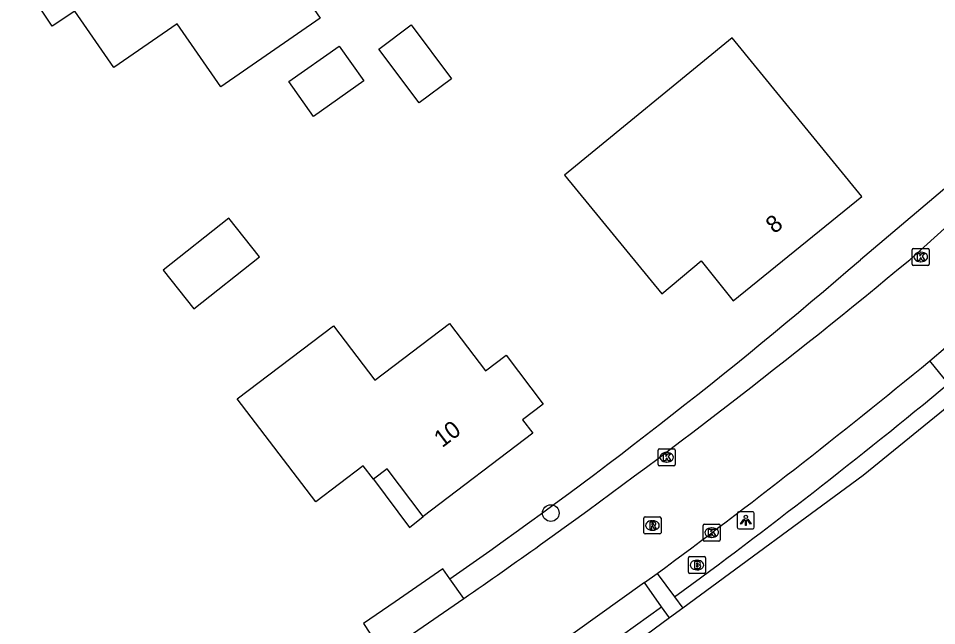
# Model space of a CAD drawing. Extents: x 162675 to 163482, y 379761 to 381227.
# Drawn here: x 163198.8 to 163252.7, y 380978.5 to 381014.2 of the extents above; entities that cross this region are included whole.
import ezdxf

# ---------------------------------------------------------------- set-up
doc = ezdxf.new("R2010")
doc.units = 0
for name, color, linetype in [('IMGEO_Boom', 7, 'Continuous'), ('IMGEO_Brandkraan', 7, 'Continuous'), ('IMGEO_Groenvoorziening', 7, 'Continuous'), ('IMGEO_Kolk', 7, 'Continuous'), ('IMGEO_Lichtpunt', 7, 'Continuous'), ('IMGEO_Pand', 7, 'Continuous'), ('IMGEO_Pand_nummerreeks', 7, 'Continuous'), ('IMGEO_Pand_overbouw', 7, 'Continuous'), ('IMGEO_Parkeervlak_halfverhard', 7, 'Continuous'), ('IMGEO_Rijbaan_lokaal_gesloten', 7, 'Continuous'), ('IMGEO_Rijbaan_lokaal_open', 7, 'Continuous'), ('IMGEO_Rioolput', 7, 'Continuous'), ('IMGEO_Voetpad_open', 7, 'Continuous')]:
    doc.layers.add(name, color=color, linetype=linetype)

msp = doc.modelspace()

# ---------------------------------------------------------------- linework, layer by layer
at = {"layer": 'IMGEO_Boom'}
msp.add_circle((163230.072, 380985.135), 0.489, dxfattribs=at)
at = {"layer": 'IMGEO_Brandkraan'}
for p, q in [((163238.222, 380982.585), (163239.074, 380982.585)), ((163238.147, 380981.659), (163238.147, 380982.511)), ((163238.635, 380982.365), (163238.66, 380982.365)), ((163239.148, 380982.511), (163239.148, 380981.659)), ((163239.074, 380981.585), (163238.222, 380981.585)), ((163238.658, 380981.805), (163238.633, 380981.805))]:
    msp.add_line(p, q, dxfattribs=at)
for points in [[(163238.222, 380982.585), (163239.074, 380982.585)], [(163238.147, 380981.659), (163238.147, 380982.511)], [(163238.495, 380982.285), (163238.495, 380981.885), (163238.708, 380981.885)], [(163238.726, 380982.285), (163238.495, 380982.285)], [(163238.674, 380982.204), (163238.62, 380982.204), (163238.62, 380982.128)], [(163238.62, 380982.128), (163238.673, 380982.128)], [(163238.682, 380982.052), (163238.62, 380982.052), (163238.62, 380981.971)], [(163239.148, 380982.511), (163239.148, 380981.659)], [(163239.074, 380981.585), (163238.222, 380981.585)], [(163238.62, 380981.971), (163238.682, 380981.971)]]:
    msp.add_lwpolyline(points, dxfattribs=at)
for centre, radius, start, end in [((163238.224, 380982.509), 0.0765, 91.552, 178.448), ((163238.224, 380982.509), 0.0765, 91.552, 178.448), ((163239.072, 380982.509), 0.0765, 1.552, 88.448), ((163239.072, 380982.509), 0.0765, 1.552, 88.448), ((163238.675, 380982.166), 0.0379, 267.8285, 90.9355), ((163238.683, 380982.011), 0.0404, 269.8759, 90.5077), ((163238.73, 380982.14), 0.145, 59.4692, 91.5367), ((163238.755, 380982.187), 0.0922, 285.5137, 58.1501), ((163238.76, 380981.995), 0.105, 301.3115, 78.989), ((163238.224, 380981.661), 0.0765, 181.552, 268.448), ((163238.224, 380981.661), 0.0765, 181.552, 268.448), ((163238.714, 380982.136), 0.251, 268.6676, 293.5347), ((163239.072, 380981.661), 0.0765, 271.552, 358.448), ((163239.072, 380981.661), 0.0765, 271.552, 358.448)]:
    msp.add_arc(centre, radius, start, end, dxfattribs=at)
for centre, major_axis, ratio, start_param, end_param in [((163238.634, 380982.085), (-0.387, 0.002), 0.722429, 4.712389, 7.853982), ((163238.659, 380982.085), (-0.39, 0.002), 0.717154, 1.570796, 4.712389)]:
    msp.add_ellipse(centre, major_axis=major_axis, ratio=ratio, start_param=start_param, end_param=end_param, dxfattribs=at)
at = {"layer": 'IMGEO_Groenvoorziening'}
for points in [[(163282.912, 381031.92), (163281.455, 381030.578), (163266.746, 381016.75), (163259.983, 381010.203), (163254.178, 381005.02), (163248.231, 381000)], [(163254.038, 380991.932), (163248.395, 380987.338), (163237.811, 380979.548)], [(163237.042, 380978.982), (163231.716, 380975.062)]]:
    msp.add_lwpolyline(points, dxfattribs=at)
msp.add_arc((163058.673, 381218.917), 289.58, 304.85117, 310.88892, dxfattribs=at)
at = {"layer": 'IMGEO_Kolk'}
for p, q in [((163251.27, 380999.734), (163251.27, 381000.586)), ((163251.345, 381000.66), (163252.197, 381000.66)), ((163251.758, 381000.44), (163251.783, 381000.44)), ((163252.271, 381000.586), (163252.271, 380999.734)), ((163251.781, 380999.88), (163251.756, 380999.88)), ((163252.197, 380999.66), (163251.345, 380999.66)), ((163236.368, 380987.982), (163236.368, 380988.834)), ((163236.443, 380988.908), (163237.295, 380988.908)), ((163236.856, 380988.688), (163236.881, 380988.688)), ((163237.369, 380988.834), (163237.369, 380987.982)), ((163236.879, 380988.128), (163236.854, 380988.128)), ((163237.295, 380987.908), (163236.443, 380987.908)), ((163239.01, 380983.558), (163239.01, 380984.41)), ((163239.085, 380984.484), (163239.937, 380984.484)), ((163239.498, 380984.264), (163239.523, 380984.264)), ((163240.011, 380984.41), (163240.011, 380983.558)), ((163239.521, 380983.704), (163239.496, 380983.704)), ((163239.937, 380983.484), (163239.085, 380983.484))]:
    msp.add_line(p, q, dxfattribs=at)
for points in [[(163251.27, 380999.734), (163251.27, 381000.586)], [(163251.345, 381000.66), (163252.197, 381000.66)], [(163251.591, 381000.36), (163251.714, 381000.36), (163251.714, 381000.209), (163251.844, 381000.36), (163252.008, 381000.36), (163251.862, 381000.209), (163252.015, 380999.96), (163251.863, 380999.96), (163251.778, 381000.124), (163251.714, 381000.057), (163251.714, 380999.96), (163251.591, 380999.96), (163251.591, 381000.36)], [(163252.271, 381000.586), (163252.271, 380999.734)], [(163252.197, 380999.66), (163251.345, 380999.66)], [(163236.368, 380987.982), (163236.368, 380988.834)], [(163236.443, 380988.908), (163237.295, 380988.908)], [(163236.689, 380988.608), (163236.812, 380988.608), (163236.812, 380988.457), (163236.942, 380988.608), (163237.106, 380988.608), (163236.96, 380988.457), (163237.113, 380988.208), (163236.961, 380988.208), (163236.876, 380988.372), (163236.812, 380988.305), (163236.812, 380988.208), (163236.689, 380988.208), (163236.689, 380988.608)], [(163237.369, 380988.834), (163237.369, 380987.982)], [(163237.295, 380987.908), (163236.443, 380987.908)], [(163239.01, 380983.558), (163239.01, 380984.41)], [(163239.085, 380984.484), (163239.937, 380984.484)], [(163240.011, 380984.41), (163240.011, 380983.558)], [(163239.331, 380984.184), (163239.454, 380984.184), (163239.454, 380984.033), (163239.584, 380984.184), (163239.748, 380984.184), (163239.602, 380984.033), (163239.755, 380983.784), (163239.603, 380983.784), (163239.518, 380983.948), (163239.454, 380983.881), (163239.454, 380983.784), (163239.331, 380983.784), (163239.331, 380984.184)], [(163239.937, 380983.484), (163239.085, 380983.484)]]:
    msp.add_lwpolyline(points, dxfattribs=at)
for centre, start, end in [((163251.347, 381000.584), 91.552, 178.448), ((163251.347, 381000.584), 91.552, 178.448), ((163252.195, 381000.584), 1.552, 88.448), ((163252.195, 381000.584), 1.552, 88.448), ((163251.347, 380999.736), 181.552, 268.448), ((163251.347, 380999.736), 181.552, 268.448), ((163252.195, 380999.736), 271.552, 358.448), ((163252.195, 380999.736), 271.552, 358.448), ((163236.445, 380988.832), 91.552, 178.448), ((163236.445, 380988.832), 91.552, 178.448), ((163237.293, 380988.832), 1.552, 88.448), ((163237.293, 380988.832), 1.552, 88.448), ((163236.445, 380987.984), 181.552, 268.448), ((163236.445, 380987.984), 181.552, 268.448), ((163237.293, 380987.984), 271.552, 358.448), ((163237.293, 380987.984), 271.552, 358.448), ((163239.087, 380984.408), 91.552, 178.448), ((163239.087, 380984.408), 91.552, 178.448), ((163239.935, 380984.408), 1.552, 88.448), ((163239.935, 380984.408), 1.552, 88.448), ((163239.087, 380983.56), 181.552, 268.448), ((163239.087, 380983.56), 181.552, 268.448), ((163239.935, 380983.56), 271.552, 358.448), ((163239.935, 380983.56), 271.552, 358.448)]:
    msp.add_arc(centre, 0.0765, start, end, dxfattribs=at)
for centre, major_axis, ratio, start_param, end_param in [((163251.757, 381000.16), (-0.387, 0.002), 0.722429, 4.712389, 7.853982), ((163251.782, 381000.16), (-0.39, 0.002), 0.717154, 1.570796, 4.712389), ((163236.855, 380988.408), (-0.387, 0.002), 0.722429, 4.712389, 7.853982), ((163236.88, 380988.408), (-0.39, 0.002), 0.717154, 1.570796, 4.712389), ((163239.497, 380983.984), (-0.387, 0.002), 0.722429, 4.712389, 7.853982), ((163239.522, 380983.984), (-0.39, 0.002), 0.717154, 1.570796, 4.712389)]:
    msp.add_ellipse(centre, major_axis=major_axis, ratio=ratio, start_param=start_param, end_param=end_param, dxfattribs=at)
at = {"layer": 'IMGEO_Lichtpunt'}
for p, q in [((163241.013, 380985.112), (163241.013, 380984.305)), ((163241.013, 380985.112), (163241.013, 380984.305)), ((163241.915, 380985.207), (163241.107, 380985.207)), ((163241.915, 380985.207), (163241.107, 380985.207)), ((163242.009, 380984.305), (163242.009, 380985.112)), ((163242.009, 380984.305), (163242.009, 380985.112)), ((163241.107, 380984.211), (163241.915, 380984.211)), ((163241.107, 380984.211), (163241.915, 380984.211))]:
    msp.add_line(p, q, dxfattribs=at)
for points in [[(163241.387, 380984.776), (163241.426, 380984.748), (163241.238, 380984.486), (163241.2, 380984.513), (163241.387, 380984.776)], [(163241.599, 380984.748), (163241.637, 380984.775), (163241.824, 380984.513), (163241.785, 380984.485), (163241.599, 380984.748)], [(163241.489, 380984.728), (163241.536, 380984.728), (163241.536, 380984.406), (163241.489, 380984.406), (163241.489, 380984.728)]]:
    msp.add_lwpolyline(points, dxfattribs=at)
msp.add_circle((163241.512, 380984.91), 0.0994, dxfattribs=at)
for centre, start, end in [((163241.107, 380985.112), 90, 180), ((163241.107, 380985.112), 90, 180), ((163241.915, 380985.112), 0, 90), ((163241.915, 380985.112), 0, 90), ((163241.107, 380984.305), 180, 270), ((163241.107, 380984.305), 180, 270), ((163241.915, 380984.305), 270, 0), ((163241.915, 380984.305), 270, 360)]:
    msp.add_arc(centre, 0.0946, start, end, dxfattribs=at)
at = {"layer": 'IMGEO_Pand'}
for points in [[(163216.549, 381014.172), (163210.72, 381010.136), (163208.153, 381013.844), (163204.436, 381011.271), (163202.152, 381014.57), (163200.83, 381013.694), (163198.84, 381016.694), (163200.116, 381017.54), (163199.546, 381018.361), (163203.321, 381020.977), (163203.891, 381020.155), (163206.772, 381022.138), (163209.333, 381018.435), (163212.214, 381020.433), (163216.549, 381014.172)], [(163219.991, 381012.346), (163221.872, 381013.775), (163224.243, 381010.614), (163222.354, 381009.197), (163219.991, 381012.346)], [(163236.593, 380998.002), (163238.893, 380999.927), (163240.777, 380997.592), (163248.313, 381003.716), (163240.711, 381013.015), (163230.875, 381004.965), (163236.593, 380998.002)], [(163216.143, 381008.407), (163214.704, 381010.446), (163217.663, 381012.533), (163219.101, 381010.493), (163216.143, 381008.407)], [(163207.332, 380999.388), (163209.133, 380997.114), (163212.983, 381000.163), (163211.182, 381002.437), (163207.332, 380999.388)], [(163224.127, 380996.263), (163226.243, 380993.477), (163227.446, 380994.39), (163229.622, 380991.525), (163228.421, 380990.613), (163229.026, 380989.817), (163222.587, 380984.931), (163220.472, 380987.722), (163219.676, 380987.115), (163219.073, 380987.913), (163216.292, 380985.792), (163211.684, 380991.836), (163217.329, 380996.122), (163219.748, 380992.938), (163224.127, 380996.263)]]:
    msp.add_lwpolyline(points, dxfattribs=at)
at = {"layer": 'IMGEO_Pand_overbouw'}
msp.add_lwpolyline([(163219.676, 380987.115), (163221.791, 380984.29), (163222.587, 380984.931), (163220.472, 380987.722)], close=True, dxfattribs=at)
at = {"layer": 'IMGEO_Parkeervlak_halfverhard'}
msp.add_lwpolyline([(163231.219, 380975.805), (163236.566, 380979.628)], dxfattribs=at)
msp.add_arc((163038.879, 381251.775), 336.342, 306.1573, 309.62868, dxfattribs=at)
at = {"layer": 'IMGEO_Rijbaan_lokaal_gesloten'}
for points in [[(163283.96, 381030.703), (163274.447, 381021.832), (163256.625, 381004.958), (163251.131, 380999.999)], [(163252.298, 380994.062), (163253.218, 380994.843)], [(163235.565, 380981.053), (163236.302, 380981.59)], [(163235.565, 380981.053), (163230.185, 380977.209)], [(163220.253, 380976.891), (163221.325, 380977.616), (163221.696, 380977.871), (163224.966, 380980.12)]]:
    msp.add_lwpolyline(points, dxfattribs=at)
for centre, radius, start, end in [((163002.35, 381300.051), 389.773, 305.63961, 309.66302), ((163009.458, 381289.023), 382.065, 306.42229, 309.46444), ((162993.378, 381314.308), 406.589, 304.72145, 305.49645)]:
    msp.add_arc(centre, radius, start, end, dxfattribs=at)
at = {"layer": 'IMGEO_Rijbaan_lokaal_open'}
for points in [[(163224.153, 380981.276), (163223.746, 380981.856), (163220.946, 380979.931), (163219.083, 380978.649), (163219.461, 380978.08)], [(163224.966, 380980.12), (163224.153, 380981.276)]]:
    msp.add_lwpolyline(points, dxfattribs=at)
at = {"layer": 'IMGEO_Rioolput'}
for p, q in [((163235.535, 380983.982), (163235.535, 380984.834)), ((163235.61, 380984.908), (163236.462, 380984.908)), ((163236.536, 380984.834), (163236.536, 380983.982)), ((163236.023, 380984.688), (163236.048, 380984.688)), ((163236.462, 380983.908), (163235.61, 380983.908)), ((163236.046, 380984.128), (163236.021, 380984.128))]:
    msp.add_line(p, q, dxfattribs=at)
for points in [[(163235.535, 380983.982), (163235.535, 380984.834)], [(163235.61, 380984.908), (163236.462, 380984.908)], [(163236.536, 380984.834), (163236.536, 380983.982)], [(163236.124, 380984.606), (163235.872, 380984.608), (163235.872, 380984.208)], [(163235.872, 380984.208), (163235.996, 380984.208), (163235.996, 380984.37), (163236.007, 380984.37)], [(163236.05, 380984.527), (163235.996, 380984.527), (163235.996, 380984.446)], [(163235.996, 380984.446), (163236.048, 380984.446)], [(163236.054, 380984.341), (163236.125, 380984.208), (163236.265, 380984.208), (163236.2, 380984.334)], [(163236.462, 380983.908), (163235.61, 380983.908)]]:
    msp.add_lwpolyline(points, dxfattribs=at)
for centre, radius, start, end in [((163235.612, 380984.832), 0.0765, 91.552, 178.448), ((163235.612, 380984.832), 0.0765, 91.552, 178.448), ((163236.46, 380984.832), 0.0765, 1.552, 88.448), ((163236.46, 380984.832), 0.0765, 1.552, 88.448), ((163236.006, 380984.317), 0.0533, 26.0293, 88.6989), ((163236.032, 380984.635), 0.19, 274.7715, 282.9687), ((163236.056, 380984.431), 0.0964, 77.0061, 93.1865), ((163236.07, 380984.488), 0.0378, 276.6634, 79.6772), ((163236.123, 380984.496), 0.109, 350.3612, 89.416), ((163236.121, 380984.496), 0.112, 277.5842, 350.9817), ((163236.105, 380984.281), 0.108, 29.5134, 73.7905), ((163235.612, 380983.984), 0.0765, 181.552, 268.448), ((163235.612, 380983.984), 0.0765, 181.552, 268.448), ((163236.46, 380983.984), 0.0765, 271.552, 358.448), ((163236.46, 380983.984), 0.0765, 271.552, 358.448)]:
    msp.add_arc(centre, radius, start, end, dxfattribs=at)
for centre, major_axis, ratio, start_param, end_param in [((163236.022, 380984.408), (-0.387, 0.002), 0.722429, 4.712389, 7.853982), ((163236.047, 380984.408), (-0.39, 0.002), 0.717154, 1.570796, 4.712389)]:
    msp.add_ellipse(centre, major_axis=major_axis, ratio=ratio, start_param=start_param, end_param=end_param, dxfattribs=at)
at = {"layer": 'IMGEO_Voetpad_open'}
for points in [[(163253.401, 380992.726), (163252.298, 380994.062)], [(163236.302, 380981.59), (163237.322, 380980.212)], [(163236.566, 380979.628), (163235.565, 380981.053)], [(163237.322, 380980.212), (163237.811, 380979.548)], [(163237.042, 380978.982), (163236.566, 380979.628)], [(163237.811, 380979.548), (163237.042, 380978.982)]]:
    msp.add_lwpolyline(points, dxfattribs=at)

# ---------------------------------------------------------------- texts
at = {"layer": 'IMGEO_Pand_nummerreeks'}
for s, rotation, p in [('8', 39.0986, (163243.188, 381001.484)), ('10', 37.1938, (163223.699, 380988.939))]:
    msp.add_text(s, height=1, rotation=rotation, dxfattribs=at).set_placement(p)

doc.saveas('drawing.dxf')
